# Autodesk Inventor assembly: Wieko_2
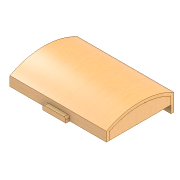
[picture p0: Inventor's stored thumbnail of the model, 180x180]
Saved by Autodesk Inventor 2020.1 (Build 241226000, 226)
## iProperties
Created: 2005-09
Part Number: Wieko_2
Document SubType Name: Assembly
Designer: F.Stasiak
Manager: www.cadconsulting.pl
Company: Fabian Stasiak CAD Consulting
Author: F.Stasiak
Subject: Zbiór ćwiczeń. Autodesk Inventor 2020. Kurs podstawowy
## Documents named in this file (4)
- C:\2020_Kurs_podstawowy\R6 Zespoły\Wiązania\Skrzynia I\Wieko_2.iam
- C:\2020_Kurs_podstawowy\R6 Zespoły\Wiązania\Skrzynia I\Bok wieka.ipt
- C:\2020_Kurs_podstawowy\R6 Zespoły\Wiązania\Skrzynia I\Wierzch wieka.ipt
- C:\2020_Kurs_podstawowy\R6 Zespoły\Wiązania\Skrzynia I\Uchwyt_1.ipt
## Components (4 placed, 3 different names)
1. Wierzch wieka:1 — Zestawiające:1, Zestawiające:2, Równoległe:1, Zestawiające:3, Zestawiające:4, Równoległe:2, Równoległe:5
2. Bok wieka:1 — Zestawiające:1, Zestawiające:2, Równoległe:1
3. Bok wieka:2 — Zestawiające:3, Zestawiające:4, Równoległe:2
4. Uchwyt_1:1 — Równoległe:5
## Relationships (7: Mate 4, Flush 3)
- Zestawiające:1 [Mate]: Wierzch wieka:1 ↔ Bok wieka:1
- Zestawiające:2 [Mate]: Wierzch wieka:1 ↔ Bok wieka:1
- Równoległe:1 [Flush]: Wierzch wieka:1 ↔ Bok wieka:1
- Zestawiające:3 [Mate]: Wierzch wieka:1 ↔ Bok wieka:2
- Zestawiające:4 [Mate]: Wierzch wieka:1 ↔ Bok wieka:2
- Równoległe:2 [Flush]: Wierzch wieka:1 ↔ Bok wieka:2
- Równoległe:5 [Flush]: Wierzch wieka:1 ↔ Uchwyt_1:1
